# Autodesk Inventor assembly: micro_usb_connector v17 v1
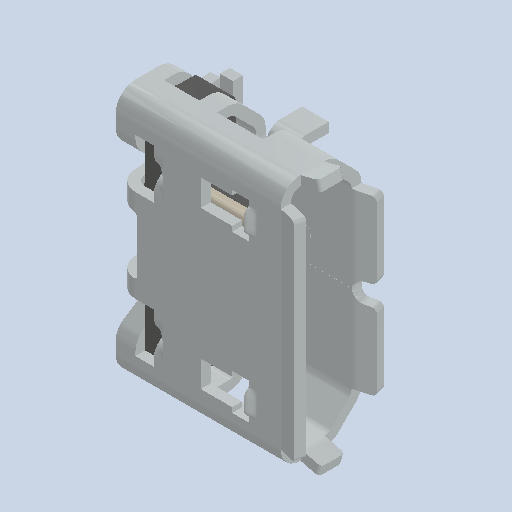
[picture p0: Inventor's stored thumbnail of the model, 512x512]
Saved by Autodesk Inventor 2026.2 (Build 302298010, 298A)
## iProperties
Created: 2026-10
Part Number: micro_usb_connector v17 v1
Document SubType Name: Assembly
Designer: mel
Author: mel
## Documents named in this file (9)
- D:\travail\année 2026-2027\1 sti2d IT\poubelle à verre\raspberry-pico-2-microcontroller-rp2350-1.snapshot.5\raspberry_pico_2\raspberry_pico_2\micro_usb_connector v17 v1.iam
- D:\travail\année 2026-2027\1 sti2d IT\poubelle à verre\raspberry-pico-2-microcontroller-rp2350-1.snapshot.5\raspberry_pico_2\raspberry_pico_2\shield.ipt
- D:\travail\année 2026-2027\1 sti2d IT\poubelle à verre\raspberry-pico-2-microcontroller-rp2350-1.snapshot.5\raspberry_pico_2\raspberry_pico_2\socket_housing.ipt
- D:\travail\année 2026-2027\1 sti2d IT\poubelle à verre\raspberry-pico-2-microcontroller-rp2350-1.snapshot.5\raspberry_pico_2\raspberry_pico_2\socket_plate.ipt
- D:\travail\année 2026-2027\1 sti2d IT\poubelle à verre\raspberry-pico-2-microcontroller-rp2350-1.snapshot.5\raspberry_pico_2\raspberry_pico_2\terminal.ipt
- D:\travail\année 2026-2027\1 sti2d IT\poubelle à verre\raspberry-pico-2-microcontroller-rp2350-1.snapshot.5\raspberry_pico_2\raspberry_pico_2\terminal001.ipt
- D:\travail\année 2026-2027\1 sti2d IT\poubelle à verre\raspberry-pico-2-microcontroller-rp2350-1.snapshot.5\raspberry_pico_2\raspberry_pico_2\terminal002.ipt
- D:\travail\année 2026-2027\1 sti2d IT\poubelle à verre\raspberry-pico-2-microcontroller-rp2350-1.snapshot.5\raspberry_pico_2\raspberry_pico_2\terminal003.ipt
- D:\travail\année 2026-2027\1 sti2d IT\poubelle à verre\raspberry-pico-2-microcontroller-rp2350-1.snapshot.5\raspberry_pico_2\raspberry_pico_2\terminal004.ipt
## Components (8 placed, 8 different names)
1. 2633
2. 2634
3. 2635
4. 2636
5. 2637
6. 2638
7. 2639
8. 2640
